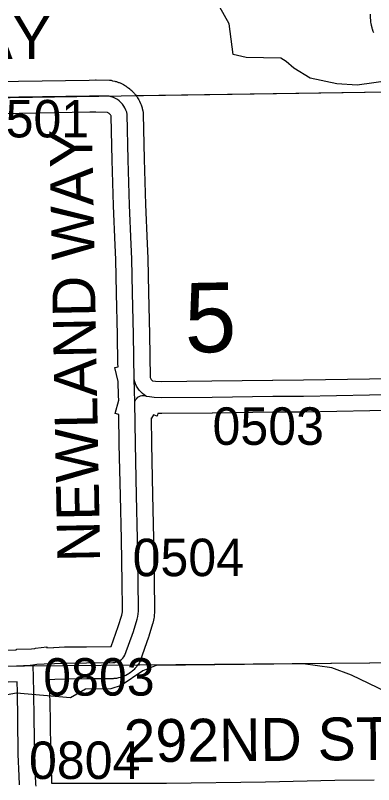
# Model space of a CAD drawing. Extents: x 23.6 to 68.7, y -63 to -29.
# Drawn here: x 46.003 to 46.673, y -52.848 to -51.412 of the extents above; entities that cross this region are included whole.
import ezdxf

# ---------------------------------------------------------------- set-up
doc = ezdxf.new("R2010")
doc.units = 0
for name, color, linetype in [('tdCoHydroRiver', 7, 'Continuous'), ('tdCoSecRdNmbr', 7, 'Continuous'), ('tdCoSecRdTxt', 7, 'Continuous'), ('tdCoSecRteBand', 7, 'Continuous'), ('tdCoSecRteCL', 7, 'Continuous'), ('tdCoSectLine', 7, 'Continuous'), ('tdCoSectLinePart', 7, 'Continuous'), ('tdCoSectNmbr', 7, 'Continuous'), ('tdCoSurfGravel', 7, 'Continuous'), ('tdCoTwpBndry', 7, 'Continuous'), ('tdCoTwpBndryShd', 7, 'Continuous')]:
    doc.layers.add(name, color=color, linetype=linetype)

msp = doc.modelspace()

# ---------------------------------------------------------------- linework, layer by layer
at = {"layer": 'tdCoHydroRiver'}
for points in [[(46.5088, -51.4974), (46.4992, -51.4912), (46.4341, -51.4903), (46.4102, -51.4843), (46.4028, -51.4275), (46.3848, -51.3961), (46.3087, -51.3116), (46.2818, -51.3087), (46.2547, -51.2869), (46.218, -51.2447), (46.1862, -51.2324), (46.1279, -51.2409), (46.0965, -51.2507), (46.0521, -51.2354), (46.0251, -51.2215), (45.9588, -51.2175), (45.8987, -51.2056), (45.8242, -51.1811), (45.813, -51.1702), (45.8016, -51.1403), (45.7777, -51.1122), (45.7093, -51.0656), (45.6014, -51.0162)], [(47.5441, -51.8273), (47.4934, -51.8168), (47.3812, -51.807), (47.3132, -51.7888), (47.1879, -51.7349), (47.0671, -51.6636), (47.0081, -51.6122), (46.9433, -51.5971), (46.8861, -51.5693), (46.8495, -51.5381), (46.8178, -51.5274), (46.7847, -51.5357), (46.7658, -51.5406), (46.7264, -51.5411), (46.7039, -51.5334), (46.6418, -51.5419), (46.6035, -51.5391), (46.5539, -51.5286), (46.5234, -51.5099), (46.5088, -51.4974)], [(46.9497, -52.7652), (46.8752, -52.7344), (46.8339, -52.7096), (46.7879, -52.6896), (46.6962, -52.6748), (46.6311, -52.644), (46.5946, -52.6302), (46.5409, -52.6229), (46.2663, -52.6259), (46.2411, -52.6356), (46.2004, -52.6629), (46.1815, -52.6694), (46.1341, -52.6699), (46.1059, -52.686), (46.0048, -52.6777), (45.9276, -52.6911)]]:
    msp.add_lwpolyline(points, dxfattribs=at)
at = {"layer": 'tdCoSecRteBand'}
for points in [[(46.6729, -51.4439), (46.6724, -51.4427), (46.672, -51.4415), (46.6705, -51.4372), (46.6701, -51.436), (46.6698, -51.4347), (46.6687, -51.4303), (46.6683, -51.429), (46.6681, -51.4277), (46.6674, -51.4232), (46.6672, -51.4219), (46.6671, -51.4206), (46.6668, -51.416), (46.6667, -51.4147), (46.6668, -51.4134), (46.6668, -51.409)], [(45.8626, -51.5369), (46.0089, -51.5346), (46.1409, -51.5323), (46.141, -51.5323), (46.141, -51.5323), (46.1529, -51.5321), (46.1535, -51.5321), (46.1541, -51.5321), (46.1788, -51.5327), (46.1817, -51.5328), (46.1845, -51.5335), (46.1887, -51.5344), (46.1902, -51.5347), (46.1916, -51.5352), (46.1956, -51.5366), (46.1971, -51.5371), (46.1985, -51.5377), (46.2024, -51.5394), (46.2038, -51.5401), (46.2051, -51.5408), (46.2087, -51.543), (46.2101, -51.5438), (46.2113, -51.5447), (46.2147, -51.5472), (46.216, -51.5481), (46.2171, -51.5491), (46.2203, -51.5519), (46.2214, -51.5529), (46.2224, -51.5541), (46.2253, -51.5572), (46.2263, -51.5584), (46.2272, -51.5596), (46.2297, -51.563), (46.2307, -51.5642), (46.2314, -51.5656), (46.2336, -51.5692), (46.2344, -51.5705), (46.235, -51.5719), (46.2368, -51.5758), (46.2374, -51.5772), (46.2379, -51.5786), (46.2393, -51.5826), (46.2398, -51.5841), (46.2401, -51.5856), (46.2411, -51.5897), (46.2417, -51.5927), (46.2418, -51.5957), (46.2438, -51.6803), (46.2462, -51.7647), (46.2495, -51.8383), (46.2495, -51.8383), (46.2495, -51.8383), (46.2507, -51.8651), (46.2507, -51.8655), (46.2507, -51.8659), (46.2518, -51.9294), (46.2537, -52.0068), (46.2537, -52.0068), (46.2537, -52.0069), (46.2551, -52.0877), (46.2554, -52.0888), (46.256, -52.0901), (46.2568, -52.0913), (46.2576, -52.0925), (46.2585, -52.0935), (46.2592, -52.0941), (46.2648, -52.095), (46.2768, -52.0954), (46.3703, -52.0943), (46.4837, -52.0926), (46.4838, -52.0926), (46.484, -52.0926), (46.5412, -52.0925), (46.6646, -52.0903), (46.6647, -52.0903), (46.6647, -52.0903), (46.7438, -52.0894)], [(46.1956, -52.1221), (46.1952, -52.0953), (46.189, -52.0693), (46.1947, -52.0679), (46.1946, -52.0621), (46.1937, -52.0081), (46.1919, -51.9307), (46.1919, -51.9306), (46.1919, -51.9306), (46.1907, -51.8673), (46.1896, -51.8409), (46.1863, -51.7671), (46.1863, -51.7669), (46.1863, -51.7667), (46.1838, -51.682), (46.1838, -51.6819), (46.1838, -51.6818), (46.1819, -51.6003), (46.1816, -51.5994), (46.1811, -51.5983), (46.1805, -51.5973), (46.1798, -51.5964), (46.179, -51.5955), (46.1782, -51.5947), (46.1772, -51.594), (46.1762, -51.5935), (46.1751, -51.593), (46.1742, -51.5926), (46.1531, -51.5921), (46.1419, -51.5922), (46.01, -51.5945), (46.0099, -51.5945), (46.0099, -51.5945), (45.8634, -51.5968)], [(45.9703, -52.5974), (46.0041, -52.5963), (46.0048, -52.5962), (46.0048, -52.5954), (46.0332, -52.5946), (46.0392, -52.5939), (46.0402, -52.5937), (46.0402, -52.5937), (46.0614, -52.591), (46.0616, -52.5926), (46.0744, -52.592), (46.0745, -52.592), (46.0745, -52.592), (46.0949, -52.5912), (46.0954, -52.5912), (46.096, -52.5912), (46.1358, -52.591), (46.1817, -52.5904), (46.1952, -52.5531), (46.2016, -52.5317), (46.2024, -52.5284), (46.2029, -52.5254), (46.2031, -52.5224), (46.2032, -52.5187), (46.2024, -52.4713), (46.2024, -52.4712), (46.2024, -52.4712), (46.2011, -52.39), (46.1991, -52.3087), (46.1991, -52.3087), (46.1991, -52.3086), (46.1971, -52.2126), (46.1971, -52.2125), (46.1971, -52.2124), (46.1964, -52.157), (46.1891, -52.155), (46.196, -52.1305), (46.1958, -52.1221), (46.1956, -52.1221)], [(46.7447, -52.1493), (46.6656, -52.1503), (46.542, -52.1525), (46.5418, -52.1525), (46.5416, -52.1525), (46.4844, -52.1526), (46.3711, -52.1543), (46.3711, -52.1543), (46.371, -52.1543), (46.2768, -52.1554), (46.2761, -52.1554), (46.2754, -52.1554), (46.269, -52.1552), (46.2676, -52.1599), (46.261, -52.1579), (46.2574, -52.1637), (46.2568, -52.1633), (46.2565, -52.1633), (46.2571, -52.2115), (46.2591, -52.3073), (46.261, -52.3886), (46.2611, -52.3888), (46.2611, -52.3889), (46.2624, -52.4702), (46.2632, -52.5182), (46.2632, -52.5188), (46.2632, -52.5193), (46.2631, -52.5245), (46.2631, -52.5256), (46.263, -52.5267), (46.2625, -52.5319), (46.2624, -52.533), (46.2622, -52.5341), (46.2614, -52.5392), (46.2612, -52.5403), (46.261, -52.5414), (46.2597, -52.5465), (46.2595, -52.5473), (46.2593, -52.5481), (46.2524, -52.5711), (46.2522, -52.5719), (46.2519, -52.5727), (46.2359, -52.6168), (46.2347, -52.6202), (46.2327, -52.6232), (46.2308, -52.626), (46.2298, -52.6276), (46.2285, -52.629), (46.2263, -52.6316), (46.2251, -52.633), (46.2237, -52.6343), (46.2211, -52.6366), (46.2198, -52.6378), (46.2182, -52.6389), (46.2154, -52.6409), (46.2139, -52.6419), (46.2123, -52.6428), (46.2092, -52.6444), (46.2076, -52.6453), (46.2058, -52.6459), (46.2026, -52.6472), (46.2009, -52.6478), (46.1991, -52.6483), (46.1957, -52.6491), (46.1939, -52.6495), (46.1921, -52.6498), (46.1887, -52.6501), (46.1871, -52.6503), (46.1856, -52.6504), (46.1364, -52.651), (46.1363, -52.651), (46.1362, -52.651), (46.0967, -52.6512), (46.0769, -52.652), (46.0663, -52.6524), (46.0668, -52.6735), (46.0668, -52.6737), (46.0668, -52.6738), (46.0676, -52.7261), (46.0676, -52.7262), (46.0676, -52.7262), (46.0683, -52.7898), (46.07, -52.8296), (46.0701, -52.8298), (46.0701, -52.8301), (46.0705, -52.8457)], [(46.0106, -52.8486), (46.0101, -52.8321), (46.0083, -52.792), (46.0083, -52.7915), (46.0083, -52.791), (46.0076, -52.7269), (46.0068, -52.6749), (46.0063, -52.6562), (46.0063, -52.6562), (46.0062, -52.6562), (45.9718, -52.6574)], [(46.0705, -52.8457), (46.1297, -52.8457), (46.2853, -52.8457), (46.4706, -52.8432), (46.6, -52.8401), (46.6001, -52.8401), (46.6003, -52.8401), (46.6733, -52.8391)]]:
    msp.add_lwpolyline(points, dxfattribs=at)
at = {"layer": 'tdCoSecRteCL'}
for points in [[(46.2251, -52.0916), (46.2237, -52.0075), (46.2219, -51.93), (46.2207, -51.8664), (46.2195, -51.8396), (46.2163, -51.7658), (46.2138, -51.6811), (46.2118, -51.5964), (46.2109, -51.5923), (46.2095, -51.5883), (46.2077, -51.5844), (46.2056, -51.5808), (46.2031, -51.5774), (46.2002, -51.5742), (46.1971, -51.5714), (46.1936, -51.5689), (46.19, -51.5668), (46.1861, -51.565), (46.1821, -51.5637), (46.178, -51.5627), (46.1533, -51.5621), (46.1415, -51.5622), (46.0094, -51.5645), (45.863, -51.5668)], [(46.2261, -52.1342), (46.2255, -52.1117), (46.2255, -52.1111), (46.2251, -52.0916)], [(46.2475, -52.1225), (46.2438, -52.1202), (46.2403, -52.1175), (46.2371, -52.1146), (46.2342, -52.1113), (46.2316, -52.1077), (46.2294, -52.104), (46.2276, -52.1), (46.2261, -52.0958), (46.2251, -52.0916)], [(46.2261, -52.1342), (46.2269, -52.1315), (46.2281, -52.129), (46.2297, -52.1268), (46.2317, -52.1248), (46.2341, -52.1233), (46.2366, -52.1222), (46.2393, -52.1215), (46.2421, -52.1213), (46.2449, -52.1217), (46.2475, -52.1225)], [(46.2475, -52.1225), (46.2536, -52.1236), (46.262, -52.1249), (46.2765, -52.1254), (46.3707, -52.1243), (46.4841, -52.1226), (46.5415, -52.1225), (46.6651, -52.1203), (46.7444, -52.1194), (46.8348, -52.1174), (46.979, -52.1131), (46.9835, -52.1126)], [(46.0355, -52.6246), (46.043, -52.6236), (46.0564, -52.6228), (46.0757, -52.622), (46.0961, -52.6212), (46.136, -52.621), (46.1852, -52.6204), (46.1886, -52.62), (46.1919, -52.6191), (46.1952, -52.6179), (46.1982, -52.6163), (46.201, -52.6143), (46.2036, -52.612), (46.2058, -52.6094), (46.2077, -52.6065), (46.2237, -52.5625), (46.2306, -52.5395), (46.2318, -52.5344), (46.2326, -52.5292), (46.2331, -52.524), (46.2332, -52.5188), (46.2324, -52.4707), (46.2311, -52.3894), (46.2291, -52.308), (46.2271, -52.212), (46.2261, -52.1342)], [(45.2346, -52.6255), (45.2459, -52.6253), (45.3579, -52.6261), (45.3974, -52.6269), (45.5544, -52.6282), (45.5703, -52.6284), (45.7201, -52.6287), (45.7546, -52.6291), (45.849, -52.6284), (45.9115, -52.6274), (45.9708, -52.6274), (46.0052, -52.6263), (46.0304, -52.6253), (46.0355, -52.6246)], [(46.0355, -52.6246), (46.0368, -52.6743), (46.0376, -52.7265), (46.0383, -52.7907), (46.0401, -52.8309), (46.0406, -52.8477), (46.0408, -52.8513)]]:
    msp.add_lwpolyline(points, dxfattribs=at)
at = {"layer": 'tdCoSectLine'}
for points in [[(45.7019, -51.569), (46.6986, -51.5546)], [(45.7323, -52.6288), (46.7374, -52.6201)]]:
    msp.add_lwpolyline(points, dxfattribs=at)
at = {"layer": 'tdCoSectLinePart'}
for points in [[(46.228, -51.5614), (46.6986, -51.5546)], [(46.2307, -52.6245), (46.7374, -52.6201)]]:
    msp.add_lwpolyline(points, dxfattribs=at)
at = {"layer": 'tdCoSurfGravel'}
for points in [[(46.2255, -52.1111), (46.2251, -52.0916), (46.2237, -52.0075), (46.2219, -51.93), (46.2207, -51.8664), (46.2195, -51.8396), (46.2163, -51.7658), (46.2138, -51.6811), (46.2118, -51.5964), (46.2109, -51.5923), (46.2095, -51.5883), (46.2077, -51.5844), (46.2056, -51.5808), (46.2031, -51.5774), (46.2002, -51.5742), (46.1971, -51.5714), (46.1936, -51.5689), (46.19, -51.5668), (46.1861, -51.565), (46.1821, -51.5637), (46.178, -51.5627), (46.1533, -51.5621), (46.1415, -51.5622), (46.0094, -51.5645), (45.863, -51.5668)], [(46.2475, -52.1225), (46.2438, -52.1202), (46.2403, -52.1175), (46.2371, -52.1146), (46.2342, -52.1113), (46.2316, -52.1077), (46.2294, -52.104), (46.2276, -52.1), (46.2261, -52.0958), (46.2251, -52.0916)], [(46.1982, -52.6163), (46.201, -52.6143), (46.2036, -52.612), (46.2058, -52.6094), (46.2077, -52.6065), (46.2237, -52.5625), (46.2306, -52.5395), (46.2318, -52.5344), (46.2326, -52.5292), (46.2331, -52.524), (46.2332, -52.5188), (46.2324, -52.4707), (46.2311, -52.3894), (46.2291, -52.308), (46.2271, -52.212), (46.2261, -52.1342), (46.2255, -52.1117), (46.2255, -52.1111)], [(46.2261, -52.1342), (46.2269, -52.1315), (46.2281, -52.129), (46.2297, -52.1268), (46.2317, -52.1248), (46.2341, -52.1233), (46.2366, -52.1222), (46.2393, -52.1215), (46.2421, -52.1213), (46.2449, -52.1217), (46.2475, -52.1225), (46.2536, -52.1236), (46.262, -52.1249), (46.2765, -52.1254), (46.3707, -52.1243), (46.4841, -52.1226), (46.5415, -52.1225), (46.6651, -52.1203), (46.7444, -52.1194), (46.8348, -52.1174), (46.979, -52.1131), (46.9835, -52.1126), (46.9835, -52.1126)], [(45.9708, -52.6274), (46.0052, -52.6263), (46.0304, -52.6253), (46.0355, -52.6246), (46.043, -52.6236), (46.0564, -52.6228), (46.0757, -52.622), (46.0961, -52.6212), (46.136, -52.621), (46.1852, -52.6204), (46.1886, -52.62), (46.1919, -52.6191), (46.1952, -52.6179), (46.1982, -52.6163)], [(46.0355, -52.6246), (46.0368, -52.6743), (46.0376, -52.7265), (46.0383, -52.7907), (46.0401, -52.8309), (46.0406, -52.8477), (46.0408, -52.8513)]]:
    msp.add_lwpolyline(points, dxfattribs=at)
at = {"layer": 'tdCoTwpBndry'}
msp.add_lwpolyline([(46.2282, -51.5614), (46.6986, -51.5546), (46.7201, -51.5546), (46.7934, -51.5533)], dxfattribs=at)
at = {"layer": 'tdCoTwpBndryShd'}
msp.add_lwpolyline([(45.7019, -51.569), (46.6986, -51.5546), (46.7201, -51.5546), (47.7309, -51.5361), (48.704, -51.5239), (48.7183, -51.5255), (49.7053, -51.5063), (50.7061, -51.4863), (51.7147, -51.4711), (52.7049, -51.4551)], dxfattribs=at)

# ---------------------------------------------------------------- texts
at = {"layer": 'tdCoSecRdNmbr'}
for s, rotation, p in [('0501', 0.0358, (45.9326, -51.6395)), ('0503', 0.0361, (46.3714, -52.2137)), ('0504', 0.036, (46.222, -52.459)), ('0803', 0.0359, (46.0549, -52.6821)), ('0804', 0.0358, (46.0283, -52.8378))]:
    msp.add_text(s, height=0.07, rotation=rotation, dxfattribs=at).set_placement(p)
at = {"layer": 'tdCoSecRdTxt'}
for s, rotation, p in [('WAY', 0.0257, (45.8255, -51.4929)), ('NEWLAND WAY', 91.0817, (46.1615, -52.432)), ('292ND ST', 0.5295, (46.2055, -52.8066))]:
    msp.add_text(s, height=0.08, rotation=rotation, dxfattribs=at).set_placement(p)
at = {"layer": 'tdCoSectNmbr'}
msp.add_text('5', height=0.13, rotation=1.036, dxfattribs=at).set_placement((46.3201, -52.0415))

doc.saveas('drawing.dxf')
